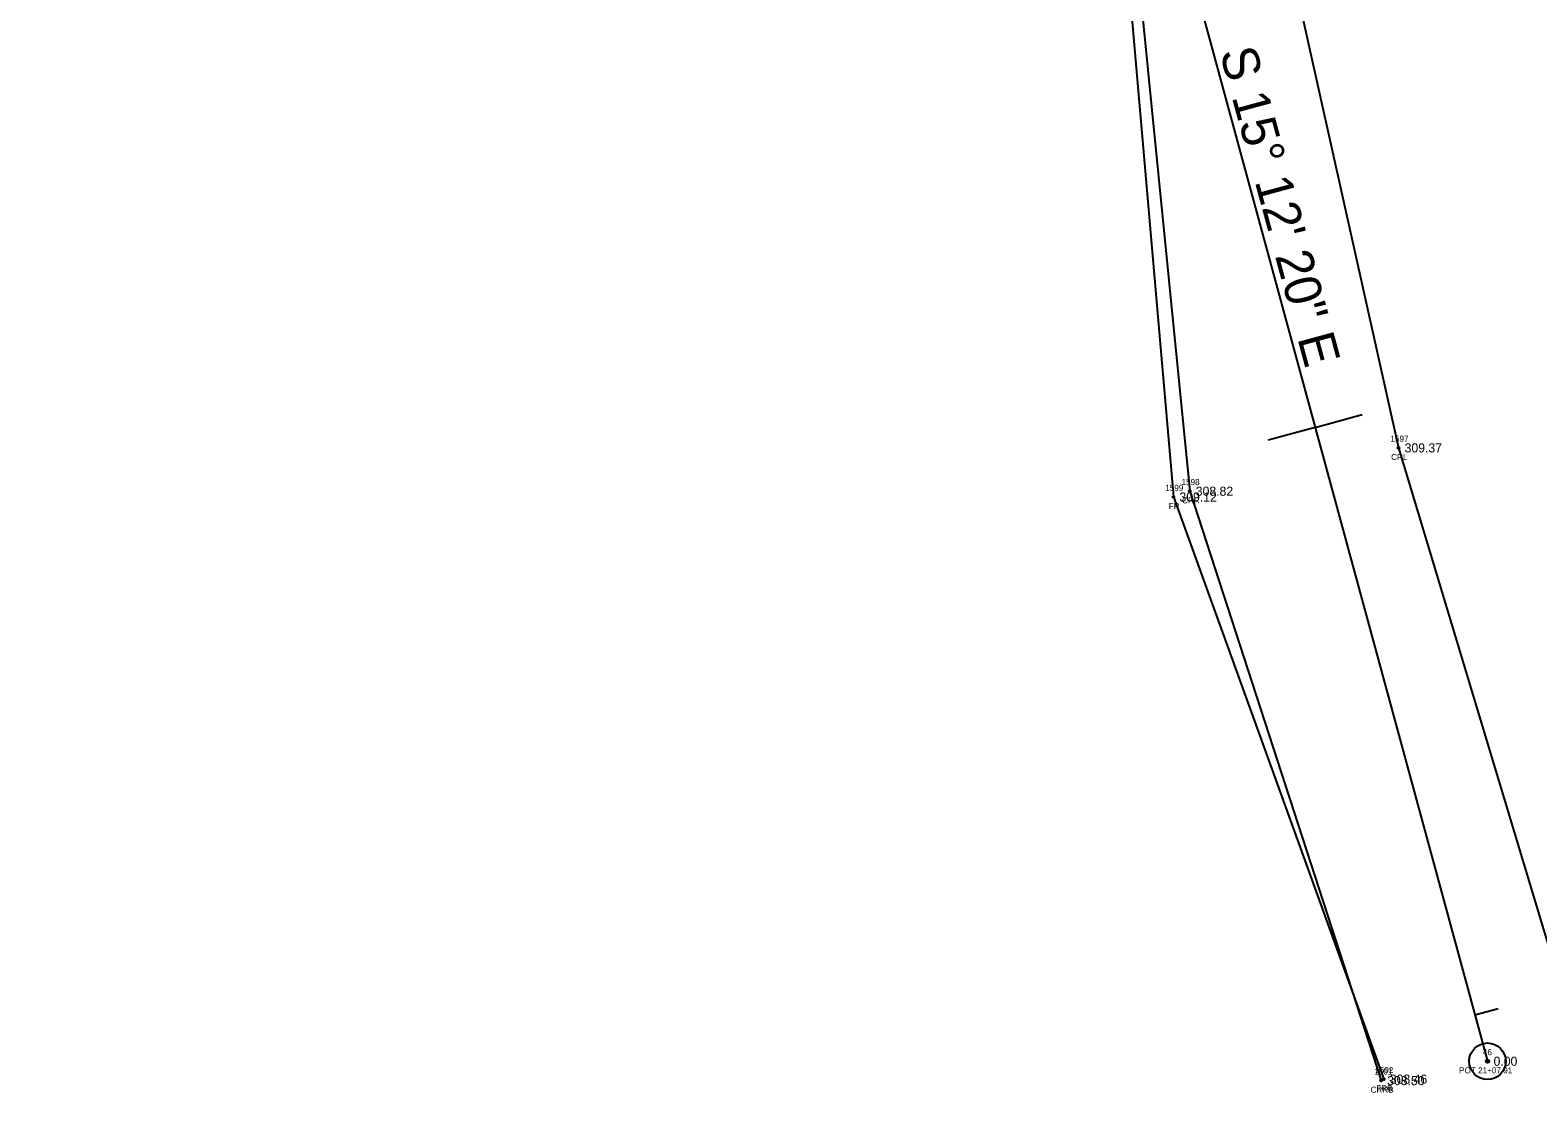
# Model space of a CAD drawing. Extents: x 1865045 to 1867370, y 910391 to 914218.
# Drawn here: x 1866180.2 to 1866427.9, y 912545.3 to 912719.8 of the extents above; entities that cross this region are included whole.
import ezdxf

# ---------------------------------------------------------------- set-up
doc = ezdxf.new("R2010")
doc.units = 0
for name, color, linetype in [('RD_EX_Fence_Other', 7, 'Continuous'), ('RD_EX_Fence_Other_txCode', 7, 'Continuous'), ('RD_EX_H2O', 7, 'Continuous'), ('RD_EX_H2O_txCode', 7, 'Continuous'), ('RD_EX_TX_Fence_Other_ELEV', 7, 'Continuous'), ('RD_EX_TX_H2O_ELEV', 7, 'Continuous'), ('RD_HC_Cl', 7, 'Continuous'), ('RD_HC_Data', 7, 'Continuous'), ('RD_HC_Data_Tic', 7, 'Continuous'), ('RD_HC_Survey_ELEV', 7, 'Continuous'), ('RD_HC_txCode', 7, 'Continuous'), ('RD_SMD_Locator', 7, 'Continuous')]:
    doc.layers.add(name, color=color, linetype=linetype)

msp = doc.modelspace()

# ---------------------------------------------------------------- linework, layer by layer
at = {"layer": 'RD_EX_Fence_Other'}
msp.add_lwpolyline([(1866203.92, 912975.29), (1866273.04, 912899.36), (1866329.04, 912821.43), (1866360.46, 912730.1), (1866368.01, 912643.16), (1866402.57, 912547.53)], dxfattribs=at)
at = {"layer": 'RD_EX_H2O'}
for points in [[(1865791.47, 913411.08), (1865848.69, 913376.33), (1865904.46, 913309.69), (1865993.96, 913244.73), (1866082.75, 913192.37), (1866116.83, 913137.71), (1866123.3, 913108.25), (1866157.61, 913053.25), (1866175.88, 913018.61), (1866222.67, 912960.01), (1866274.68, 912900.03), (1866329, 912821.99), (1866362.07, 912730.95), (1866370.69, 912644.11), (1866402.13, 912547.29)], [(1866200.61, 913176.14), (1866189.81, 913153.18), (1866155.51, 913136.72), (1866175.46, 913072.32), (1866201.64, 913040.37), (1866239.46, 912991.57), (1866296.57, 912912.84), (1866354.23, 912832), (1866384.66, 912742.4), (1866405, 912651.23), (1866435.09, 912551.21)]]:
    msp.add_lwpolyline(points, dxfattribs=at)
at = {"layer": 'RD_HC_Cl'}
msp.add_line((1866343.94, 912828.87), (1866419.61, 912550.47), dxfattribs=at)
at = {"layer": 'RD_HC_Data'}
for radius in [3, 0.282]:
    msp.add_circle((1866419.61, 912550.47), radius, dxfattribs=at)
at = {"layer": 'RD_HC_Data_Tic'}
for p, q in [((1866391.31, 912654.6), (1866399.03, 912656.7)), ((1866391.31, 912654.6), (1866383.59, 912652.5)), ((1866417.53, 912558.1), (1866421.39, 912559.15))]:
    msp.add_line(p, q, dxfattribs=at)
at = {"layer": 'RD_SMD_Locator'}
for centre in [(1866405, 912651.23), (1866368.01, 912643.16), (1866370.69, 912644.11), (1866419.61, 912550.47), (1866402.13, 912547.29), (1866402.57, 912547.53)]:
    msp.add_circle(centre, 0.15, dxfattribs=at)

# ---------------------------------------------------------------- texts
at = {"layer": 'RD_EX_Fence_Other_txCode'}
for s, p in [('1599', (1866366.67, 912644.16)), ('FR', (1866367.26, 912641.16)), ('1602', (1866401.16, 912548.53)), ('FRB', (1866401.34, 912545.53))]:
    msp.add_text(s, height=1, dxfattribs=at).set_placement(p)
at = {"layer": 'RD_EX_H2O_txCode'}
for s, p in [('1597', (1866403.66, 912652.23)), ('CRL', (1866403.78, 912649.23)), ('1598', (1866369.34, 912645.11)), ('CRR', (1866369.43, 912642.11)), ('1601', (1866401.01, 912548.29)), ('CRRB', (1866400.41, 912545.29))]:
    msp.add_text(s, height=1, dxfattribs=at).set_placement(p)
at = {"layer": 'RD_EX_TX_Fence_Other_ELEV'}
for s, p in [('309.12', (1866369.01, 912642.41)), ('308.46', (1866403.57, 912546.78))]:
    msp.add_text(s, height=1.5, dxfattribs=at).set_placement(p)
at = {"layer": 'RD_EX_TX_H2O_ELEV'}
for s, p in [('309.37', (1866406, 912650.48)), ('308.82', (1866371.69, 912643.36)), ('308.50', (1866403.13, 912546.54))]:
    msp.add_text(s, height=1.5, dxfattribs=at).set_placement(p)
at = {"layer": 'RD_HC_Data'}
msp.add_text('S 15%%d 12\' 20" E', height=6, rotation=285.2055, dxfattribs=at).set_placement((1866375.59, 912716.22))
at = {"layer": 'RD_HC_Survey_ELEV'}
msp.add_text('0.00', height=1.5, dxfattribs=at).set_placement((1866420.61, 912549.72))
at = {"layer": 'RD_HC_txCode'}
for s, p in [('46', (1866418.85, 912551.47)), ('POT 21+07.91', (1866414.94, 912548.47))]:
    msp.add_text(s, height=1, dxfattribs=at).set_placement(p)

doc.saveas('drawing.dxf')
